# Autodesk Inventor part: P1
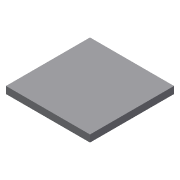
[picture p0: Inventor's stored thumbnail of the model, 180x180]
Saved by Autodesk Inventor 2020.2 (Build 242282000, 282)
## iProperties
Created: 2005-11
Part Number: P1
Document SubType Name: Modeling
Designer: F.Stasiak
Density: 1 g/cm^3
Material: Ogólny
Appearance: Domyślna
Manager: www.cadconsulting.pl
Company: Fabian Stasiak CAD Consulting
Author: F.Stasiak
Subject: Zbiór ćwiczeń. Autodesk Inventor 2020. Kurs podstawowy
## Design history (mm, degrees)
sketch "Szkic1"
  geometry: L1 (60, 60)-(60, -60); L2 (60, -60)-(-60, -60); L3 (-60, -60)-(-60, 60); L4 (-60, 60)-(60, 60); 2 further points
  constraints: 8 end point, 1 coincident, 8 other
  dimensions: "d0" = 120 distance of L1.end L2.end
extrude "Wyciągnięcie proste1" new body sketch "Szkic1" distance "d1" = 10; taper "d2" = 0 deg
node "Bryła1"
node "Korpusy bryłowe"
node "Korpusy powierzchniowe"
